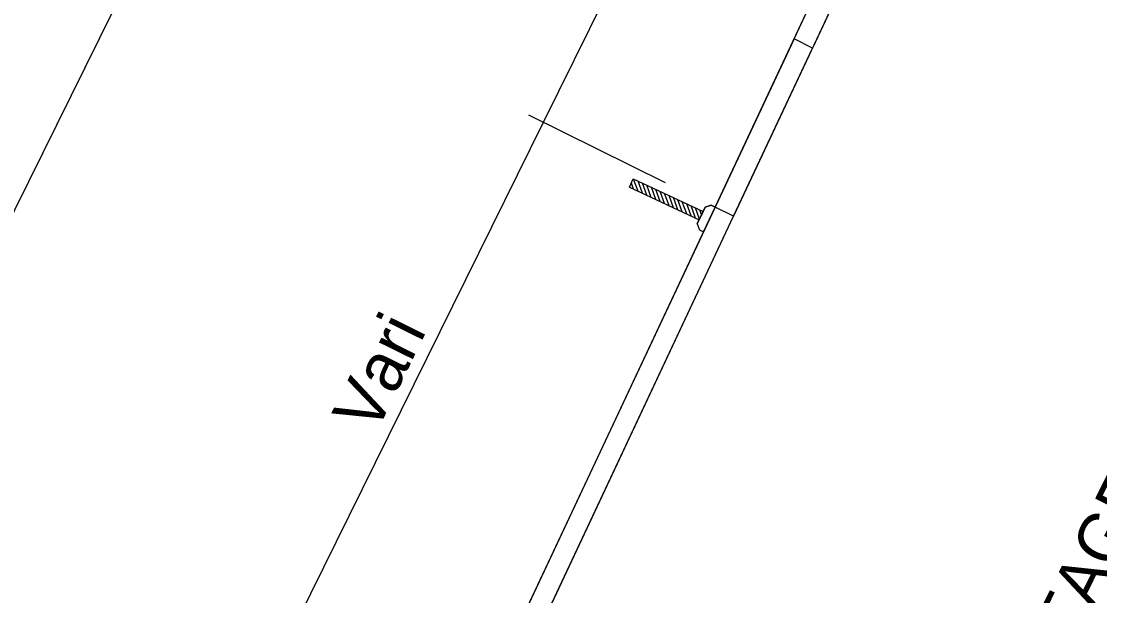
# Model space of a CAD drawing. Extents: x 14104283 to 14129344, y 8637090 to 8673339.
# Drawn here: x 14118342.5 to 14118517.6, y 8668295.3 to 8668388.5 of the extents above; entities that cross this region are included whole.
import ezdxf

# ---------------------------------------------------------------- set-up
doc = ezdxf.new("R2010")
doc.units = 0
for name, color, linetype in [('Cell', 7, 'Continuous'), ('Default', 7, 'Continuous'), ('dsnNonPlotable', 7, 'Continuous'), ('dsnStgShadingPrevPav', 7, 'Continuous'), ('dsnTextFinalPlan', 7, 'Continuous'), ('TC_SubstrataExistingPavement', 7, 'Continuous'), ('Terrain', 7, 'Continuous')]:
    doc.layers.add(name, color=color, linetype=linetype)

msp = doc.modelspace()

# ---------------------------------------------------------------- linework, layer by layer
at = {"layer": 'Cell'}
for p, q in [((14118441.25, 8668361.58), (14118441.88, 8668362.93)), ((14118441.93, 8668361.27), (14118441.57, 8668362.26)), ((14118441.88, 8668362.93), (14118453.22, 8668357.64)), ((14118442.65, 8668360.93), (14118441.93, 8668362.91)), ((14118443.37, 8668360.6), (14118442.65, 8668362.57)), ((14118444.08, 8668360.26), (14118443.37, 8668362.24)), ((14118441.25, 8668361.58), (14118452.59, 8668356.29)), ((14118444.8, 8668359.93), (14118444.09, 8668361.9)), ((14118445.52, 8668359.59), (14118444.81, 8668361.56)), ((14118446.24, 8668359.26), (14118445.52, 8668361.23)), ((14118446.96, 8668358.92), (14118446.24, 8668360.89)), ((14118447.68, 8668358.59), (14118446.96, 8668360.56)), ((14118448.4, 8668358.25), (14118447.68, 8668360.22)), ((14118449.12, 8668357.91), (14118448.4, 8668359.89)), ((14118449.84, 8668357.58), (14118449.12, 8668359.55)), ((14118450.56, 8668357.24), (14118449.84, 8668359.22)), ((14118451.27, 8668356.91), (14118450.56, 8668358.88)), ((14118451.99, 8668356.57), (14118451.28, 8668358.54)), ((14118452.65, 8668356.41), (14118452, 8668358.21)), ((14118452.28, 8668355.62), (14118453.53, 8668358.31)), ((14118453.22, 8668357.64), (14118452.59, 8668356.29)), ((14118452.98, 8668357.13), (14118452.71, 8668357.87)), ((14118453.53, 8668358.31), (14118453.22, 8668357.64)), ((14118453.3, 8668354.32), (14118455.18, 8668358.36)), ((14118453.3, 8668354.32), (14118455.18, 8668358.36)), ((14118454.52, 8668358.67), (14118453.53, 8668358.31)), ((14118453.53, 8668358.31), (14118454.52, 8668358.67)), ((14118455.18, 8668358.36), (14118454.52, 8668358.67)), ((14118454.52, 8668358.67), (14118455.18, 8668358.36)), ((14118452.59, 8668356.29), (14118452.28, 8668355.62)), ((14118452.28, 8668355.62), (14118452.63, 8668354.64)), ((14118452.28, 8668355.62), (14118452.63, 8668354.64)), ((14118452.63, 8668354.64), (14118453.3, 8668354.32)), ((14118452.63, 8668354.64), (14118453.3, 8668354.32))]:
    msp.add_line(p, q, dxfattribs=at)
at = {"layer": 'Default'}
msp.add_lwpolyline([(14118468.01, 8668385.67), (14118483.41, 8668418.45), (14118488.42, 8668429.12), (14118491.41, 8668427.64), (14118471, 8668384.19)], close=True, dxfattribs=at)
at = {"layer": 'dsnNonPlotable'}
msp.add_lwpolyline([(14118092.03, 8667853.71), (14118786.76, 8669258.84), (14119692.14, 8668811.2), (14118997.41, 8667406.07)], close=True, dxfattribs=at)
at = {"layer": 'dsnStgShadingPrevPav'}
msp.add_lwpolyline([(14118416.97, 8668269.18), (14118458.17, 8668356.88), (14118471, 8668384.19), (14118468.01, 8668385.67), (14118455.18, 8668358.36), (14118413.98, 8668270.65)], close=True, dxfattribs=at)
at = {"layer": 'dsnTextFinalPlan'}
for p, q in [((14118427.29, 8668372.15), (14118448.57, 8668415.17)), ((14118424.84, 8668373.36), (14118447.07, 8668362.37)), ((14118363.08, 8668242.27), (14118427.29, 8668372.15))]:
    msp.add_line(p, q, dxfattribs=at)
msp.add_lwpolyline([(14118092.03, 8667853.71), (14118606.59, 8668894.44), (14118787.23, 8668805.14), (14118272.66, 8667764.4)], close=True, dxfattribs=at)
at = {"layer": 'TC_SubstrataExistingPavement'}
msp.add_line((14118385.74, 8668202.69), (14118458.17, 8668356.88), dxfattribs=at)
msp.add_lwpolyline([(14118511.64, 8668478.53), (14118514.63, 8668477.06), (14118458.17, 8668356.88), (14118455.18, 8668358.36)], dxfattribs=at)
at = {"layer": 'Terrain'}
for p, q in [((14118455.18, 8668358.36), (14118511.64, 8668478.53)), ((14118382.75, 8668204.17), (14118455.18, 8668358.36))]:
    msp.add_line(p, q, dxfattribs=at)

# ---------------------------------------------------------------- texts
at = {"layer": 'dsnTextFinalPlan'}
for s, p in [('STAGE 3 - Sta. 599+00', (14118510.81, 8668280.55)), ('Vari', (14118399.92, 8668321.25))]:
    msp.add_text(s, height=8, rotation=63.6911, dxfattribs=at).set_placement(p)

doc.saveas('drawing.dxf')
